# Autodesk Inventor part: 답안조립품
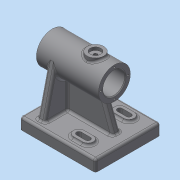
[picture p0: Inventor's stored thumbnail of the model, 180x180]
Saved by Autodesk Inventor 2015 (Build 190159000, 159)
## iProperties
Created: 2026-09
Part Number: 답안조립품
Material: 일반
Document SubType Name: Modeling
Designer: SCD-A06
Density: 1 g/cm^3
Appearance: 기본값
Author: SCD-A06
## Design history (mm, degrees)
sketch "스케치1"
  geometry: L1 (-50, -43)-(50, -43); L2 (50, -43)-(50, 43); L3 (50, 43)-(-50, 43); L4 (-50, 43)-(-50, -43); L5 (-50, -43)-(50, 43); L6 (50, -43)-(-50, 43); 1 further point
  constraints: 12 end point, 2 midpoint, 2 parallel, 1 horizontal, 1 perpendicular
  dimensions: "d0" = 100 distance of L2.end L3.end; "d1" = 86 distance of L1.end L2.end
extrude "돌출1" new body sketch "스케치1" distance "d2" = 15; taper "d3" = 0 deg
node "작업 평면1"
sketch "스케치2"
  geometry: L1 (50, 21)-(-32, 21); L2 (-32, 21)-(-32, 0); L3 (-32, 0)-(50, 0); L4 (50, 0)-(50, 21); L5 (50, 43)-(50, -43) reference; L6 (-50, -43)-(-50, 43) reference; 3 further points
  constraints: 8 end point, 2 midpoint, 2 parallel, 1 coincident, 1 collinear, 1 horizontal, 1 perpendicular, 1 point on line
  dimensions: "d5" = 82 distance of L1.start L1.end; "d7" = 42 diameter of L1 L3
revolve "회전1" sketch "스케치2" stored, may be unused: angle "d8" = 90 deg
sketch "스케치4"
  geometry: L1 (-50, -43)-(50, -43) reference; L2 (-50, 43)-(-50, -43) reference; L3 (-35, -35)-(-25, -35); L4 (-25, -35)-(-25, 35); L5 (-25, 35)-(-35, 35); L6 (-35, 35)-(-35, -35); 3 further points
  constraints: 8 end point, 2 midpoint, 2 parallel, 1 horizontal, 1 horizontal alignment, 1 perpendicular
  dimensions: "d9" = 10 distance of L3.start L3.end; "d10" = 15 distance between parallel lines of L6 L2; "d11" = 8 distance between parallel lines of L3 L1
extrude "돌출2" join sketch "스케치4" distance "d14" = 50; taper "d15" = 0 deg
sketch "스케치6"
  geometry: L1 (50, 70)-(50, 54.799) reference; L2 (0, 70)-(50, 70) reference; L3 (50, 15.201)-(50, 0) reference; L4 (0, 70)-(61.814, 55.441); L5 (0, 70)-(61.814, 70); L6 (61.814, 70)-(61.814, 55.441); L7 (50, 58.223)-(50, 54.799); A1 r 21 centre (57, 35) between (50, 15.201) and (50, 54.799) reference; A2 r 21 centre (57, 35) between (61.814, 55.441) and (50, 54.799); 1 further point
  constraints: 9 end point, 4 point on line, 3 point on circle, 1 centre point, 1 coincident, 1 collinear, 1 concentric, 1 perpendicular, 1 tangent
extrude "돌출3" cut sketch "스케치6" distance "d16" = 50; taper "d17" = 0 deg
extrude "돌출4" join sketch "스케치6" distance "d18" = 10; taper "d19" = 0 deg
sketch "스케치9"
  geometry: L1 (50, 15)-(-50, 15) reference; L2 (-35, 15)-(-28.472, 32.936); L3 (-50, 0)-(-50, 15) reference; 1 further point
  constraints: 2 end point, 1 point on line
  dimensions: "d29" = 15 distance from line of L2.start L3; "d30" = 70 deg angle of L1 L2
feature "리브1" sketch "스케치9" dims "d31" = 1, "d32" = 10, "d33" = 0, "d34" = 0, "d35" = 1, "d36" = 1
sketch "스케치11"
  geometry: 1 further point
sketch "스케치12"
  geometry: L1 (-32, 51)-(-32, 93) reference; L2 (30, 72)-(30, 86.5); L3 (30, 86.5)-(-32, 86.5); L4 (-32, 86.5)-(-32, 72); L5 (50, 72)-(50, 84.5); L6 (50, 84.5)-(30, 84.5); L7 (30, 84.5)-(30, 72); L8 (50, 51)-(50, 93) reference; L9 (-32, 72)-(30, 72); L10 (30, 72)-(50, 72); 1 further point
  constraints: 16 end point, 2 collinear, 2 parallel, 1 horizontal, 1 midpoint
  dimensions: "d41" = 62 distance between parallel lines of L2 L1; "d42" = 29 diameter of L3 L9; "d43" = 25 diameter of L6 L10
revolve "회전2" sketch "스케치12" stored, may be unused: angle "d44" = 90 deg
chamfer "모따기1" distance "d45" = 1; stored, may be unused: second distance "d46" = 2, angle "d47" = 45 deg
node "작업 평면2"
sketch "스케치13"
  geometry: L1 (-32, -21)-(-32, 21) reference; C1 r 11 at (-7, 0); 1 further point
  constraints: 1 centre point, 1 horizontal alignment
  dimensions: "d49" = 22 diameter of C1; "d50" = 25 distance from line of L1 C1.centre
extrude "돌출7" join sketch "스케치13" stored distance "d51" = 10; taper "d52" = 0 deg
hole "구멍1" diameter "d55" = 4.917; stored, may be unused: countersink angle "d59" = 90 deg, drill point angle "d61" = 118 deg; dims "d56" = 12, "d57" = 14, "d58" = 4, "d60" = 17.1, "d100" = 10, "d101" = 10
sketch "스케치14"
  geometry: C1 r 15.5 at (0, 0) reference; A1 r 18 centre (0, 0) between (-18, 0) and (0, 18); 3 further points
  constraints: 4 point on circle, 1 centre point, 1 coincident
  dimensions: "d62" = 36 diameter of A1
hole "구멍2" sketch "스케치14" at (-18, 0), (0, 18), (18, 0), (0, -18) diameter "d63" = 2.459; stored, may be unused: countersink angle "d67" = 82 deg, drill point angle "d69" = 118 deg; dims "d64" = 8, "d65" = 3.023, "d66" = 4, "d68" = 10
sketch "스케치15"
  geometry: C1 r 13.5 at (0, 0) reference; A1 r 18 centre (0, 0) between (18, 0) and (0, 18); 3 further points
  constraints: 4 point on circle, 1 centre point, 1 coincident
  dimensions: "d72" = 36 diameter of A1
hole "구멍3" sketch "스케치15" at (0, -18), (18, 0), (0, 18), (-18, 0) diameter "d73" = 2.459; stored, may be unused: countersink angle "d77" = 82 deg, drill point angle "d79" = 118 deg; dims "d74" = 8, "d75" = 3.023, "d76" = 4, "d78" = 10
sketch "스케치16"
  geometry: L1 (50, -43)-(50, 43) reference; L2 (12, 27)-(24, 27); L3 (12, 20)-(24, 20); L4 (24, 34)-(12, 34); L5 (24, -27)-(12, -27); L6 (24, -34)-(12, -34); L7 (12, -20)-(24, -20); L8 (24, 30.3)-(12, 30.3); L9 (12, 23.7)-(24, 23.7); L10 (24, -23.7)-(12, -23.7); L11 (12, -30.3)-(24, -30.3); A1 r 7 centre (12, 27) between (12, 34) and (12, 20); A2 r 7 centre (24, 27) between (24, 20) and (24, 34); A3 r 7 centre (24, -27) between (24, -34) and (24, -20); A4 r 7 centre (12, -27) between (12, -20) and (12, -34); A5 r 3.3 centre (12, 27) between (12, 30.3) and (12, 23.7); A6 r 3.3 centre (24, 27) between (24, 23.7) and (24, 30.3); A7 r 3.3 centre (12, -27) between (12, -23.7) and (12, -30.3); A8 r 3.3 centre (24, -27) between (24, -30.3) and (24, -23.7); 3 further points
  constraints: 24 end point, 16 point on circle, 8 centre point, 8 tangent, 5 parallel, 2 horizontal, 2 midpoint, 1 vertical alignment, 6 other
  dimensions: "d80" = 12 distance of L4.start L4.end; "d81" = 26 distance from line of L4.start L1; "d82" = 54 distance of L5.start L2.end; "d83" = 27 vertical distance of point (0, 0) point (18, 27) (= 0.5 x d82); "d84" = 7 radius of A2; "d85" = 7 radius of A3; "d86" = 3.7 radial gap between concentric circles of A2 A6; "d87" = 3.7 radial gap between concentric circles of A3 A8
extrude "돌출8" join sketch "스케치16" distance "d88" = 3; taper "d89" = 0 deg
extrude "돌출9" cut sketch "스케치16" stored distance "d90" = 3; taper "d91" = 0 deg
fillet "모깎기1" dims "d92" = 3
fillet "모깎기2" dims "d93" = 3
fillet "모깎기3" dims "d94" = 3
fillet "모깎기4" dims "d95" = 3
fillet "모깎기5" dims "d96" = 3
sketch "스케치17"
  geometry: L1 (0, 80)-(0, 0) reference; 3 further points
  constraints: 1 horizontal alignment, 1 midpoint, 1 other
  dimensions: "d97" = 6 distance of point (6, 40) point (0, 40)
feature "엠보싱1" sketch "스케치17" dims "d0" = 100, "d1" = 86, "d98" = 0.5, "d99" = 0
node "솔리드1"
mirror "대칭1"
other parameters: "d4" = -72, "d48" = -96
